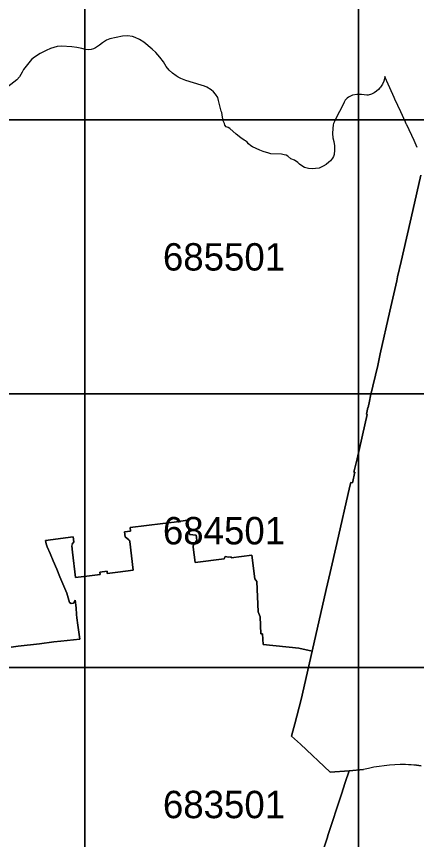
# Model space of a CAD drawing. Extents: x 25485000 to 25520000, y 6656775 to 6690000.
# Drawn here: x 25500750 to 25502211, y 6683372 to 6686378 of the extents above; entities that cross this region are included whole.
import ezdxf

# ---------------------------------------------------------------- set-up
doc = ezdxf.new("R2010")
doc.units = 0
doc.layers.add('Level 63', color=7, linetype='Continuous')

msp = doc.modelspace()

# ---------------------------------------------------------------- linework, layer by layer
at = {"layer": 'Level 63'}
for points in [[(25500000, 6686000), (25501000, 6686000), (25501000, 6687000), (25500000, 6687000)], [(25501000, 6686000), (25502000, 6686000), (25502000, 6687000), (25501000, 6687000)], [(25502000, 6686000), (25503000, 6686000), (25503000, 6687000), (25502000, 6687000)], [(25500000, 6685000), (25501000, 6685000), (25501000, 6686000), (25500000, 6686000)], [(25501000, 6685000), (25502000, 6685000), (25502000, 6686000), (25501000, 6686000)], [(25502000, 6685000), (25503000, 6685000), (25503000, 6686000), (25502000, 6686000)], [(25500000, 6684000), (25501000, 6684000), (25501000, 6685000), (25500000, 6685000)], [(25501000, 6684000), (25502000, 6684000), (25502000, 6685000), (25501000, 6685000)], [(25502000, 6684000), (25503000, 6684000), (25503000, 6685000), (25502000, 6685000)], [(25500000, 6683000), (25501000, 6683000), (25501000, 6684000), (25500000, 6684000)], [(25501000, 6683000), (25502000, 6683000), (25502000, 6684000), (25501000, 6684000)], [(25502000, 6683000), (25503000, 6683000), (25503000, 6684000), (25502000, 6684000)]]:
    msp.add_lwpolyline(points, close=True, dxfattribs=at)
for points in [[(25502214, 6685899.6), (25502202.2, 6685925), (25502175.7, 6685982.4), (25502175.2, 6685983.4), (25502173.8, 6685986.3), (25502171.5, 6685991.4), (25502153.7, 6686030.1), (25502132.6, 6686076.5), (25502130.1, 6686082), (25502102.9, 6686142), (25502102, 6686143.9), (25502095.5, 6686158.3), (25502094, 6686149.6), (25502091.6, 6686141.6), (25502086.9, 6686130.7), (25502079.6, 6686119.4), (25502077.2, 6686116.8), (25502072.5, 6686111.6), (25502065.4, 6686105.2), (25502056.8, 6686099.3), (25502046.4, 6686093.9), (25502034.6, 6686090.8), (25502029.8, 6686090.2), (25502010.1, 6686093), (25502002, 6686093.1), (25501993.7, 6686092.7), (25501977, 6686090), (25501972.2, 6686088.4), (25501963.1, 6686083.8), (25501957.6, 6686079.6), (25501950.5, 6686072.2), (25501946.6, 6686065.3), (25501942.3, 6686054.5), (25501930.4, 6686030.7), (25501922, 6686014.9), (25501911.6, 6685994.6), (25501908.7, 6685987.5), (25501907.3, 6685982.4), (25501905.3, 6685968.9), (25501904.7, 6685951), (25501906, 6685935.1), (25501909.1, 6685920.8), (25501911.6, 6685905.4), (25501912.1, 6685889.5), (25501910.5, 6685873.9), (25501908, 6685867), (25501904.4, 6685860.4), (25501897.2, 6685851.2), (25501891.3, 6685845.6), (25501881.1, 6685837.6), (25501870.6, 6685830.7), (25501856.2, 6685824.4), (25501842.7, 6685822.3), (25501832.4, 6685821.8), (25501816.6, 6685822.4), (25501802.2, 6685826.5), (25501795.6, 6685830.1), (25501783.6, 6685838.8), (25501778, 6685844.4), (25501765.7, 6685853.6), (25501752.1, 6685858.3), (25501741.6, 6685867.5), (25501735, 6685870.8), (25501727.8, 6685873.1), (25501718.1, 6685874.7), (25501679.7, 6685876.8), (25501672.3, 6685878.6), (25501650.8, 6685884.7), (25501638.8, 6685889.4), (25501612.5, 6685901.9), (25501606.1, 6685906), (25501597.9, 6685912.7), (25501592.8, 6685918.6), (25501586.9, 6685923.2), (25501581.5, 6685925.8), (25501569.8, 6685935), (25501552.1, 6685948.6), (25501529.6, 6685968.6), (25501523.3, 6685972.7), (25501515.8, 6685974.7), (25501511.5, 6685980.9), (25501509.5, 6685986.7), (25501505.4, 6685997.3), (25501503.9, 6686002.7), (25501501.3, 6686018.7), (25501499.8, 6686027.3), (25501498.2, 6686032.6), (25501491.4, 6686056.7), (25501488.6, 6686070.7), (25501485.6, 6686081.4), (25501477.6, 6686093.9), (25501470.2, 6686102.5), (25501461.3, 6686109.7), (25501446, 6686119.2), (25501436.9, 6686123.2), (25501425.4, 6686127), (25501368.6, 6686144.4), (25501350.5, 6686151.5), (25501340.4, 6686156.6), (25501333.3, 6686161.1), (25501319.8, 6686171), (25501308.3, 6686181.6), (25501297.6, 6686194.7), (25501287.3, 6686212), (25501274.1, 6686229.4), (25501259, 6686246.6), (25501246.1, 6686258.9), (25501215.3, 6686283.8), (25501199.6, 6686294.1), (25501184.2, 6686301.2), (25501174, 6686304.2), (25501156.3, 6686307.3), (25501138.1, 6686306.4), (25501091.1, 6686296), (25501079.3, 6686291.1), (25501064.2, 6686281.8), (25501053.5, 6686273.5), (25501039.2, 6686263.2), (25501031.5, 6686259.6), (25501023.1, 6686257.1), (25501014.5, 6686256.5), (25501002.1, 6686257.7), (25500989.6, 6686261.1), (25500970.4, 6686264.7), (25500952.4, 6686267.3), (25500914.7, 6686269.8), (25500899.1, 6686268.4), (25500874.5, 6686260.7), (25500858.9, 6686254), (25500836.4, 6686242.2), (25500815.8, 6686229.8), (25500805.3, 6686220.9), (25500776.4, 6686184.3), (25500770.6, 6686175), (25500760.9, 6686157.8), (25500752.1, 6686146.3), (25500692.4, 6686100.4)], [(25500952, 6684444.6), (25500955, 6684421.2), (25500966.4, 6684329), (25501016.4, 6684335.5), (25501056.1, 6684340.5), (25501055.2, 6684348.4), (25501081.1, 6684351.7), (25501082, 6684343.8), (25501120, 6684348.7), (25501176.6, 6684356.1), (25501164.3, 6684460.4), (25501164.3, 6684460.7), (25501164.3, 6684460.9), (25501164.2, 6684461.2), (25501164.2, 6684461.4), (25501164.1, 6684461.6), (25501164, 6684461.9), (25501164, 6684462.1), (25501163.9, 6684462.4), (25501163.8, 6684462.6), (25501163.7, 6684462.8), (25501163.6, 6684463.1), (25501163.4, 6684463.3), (25501163.3, 6684463.5), (25501163.2, 6684463.7), (25501163.1, 6684463.9), (25501162.9, 6684464.1), (25501162.8, 6684464.4), (25501162.6, 6684464.5), (25501162.4, 6684464.7), (25501162.3, 6684464.9), (25501162.1, 6684465.1), (25501161.9, 6684465.3), (25501161.7, 6684465.5), (25501161.5, 6684465.6), (25501161.3, 6684465.8), (25501161.1, 6684465.9), (25501160.9, 6684466.1), (25501160.7, 6684466.2), (25501147.3, 6684477.7), (25501145.2, 6684496.1), (25501167.1, 6684498.6), (25501165.6, 6684511.5), (25501225.1, 6684518.9), (25501284.3, 6684526.2), (25501326, 6684531.4), (25501375.5, 6684537.9), (25501382.2, 6684485.5), (25501406.2, 6684483.6), (25501408.7, 6684464.8), (25501398.7, 6684450.9), (25501398.6, 6684450.7), (25501398.4, 6684450.4), (25501398.2, 6684450.1), (25501398, 6684449.8), (25501397.8, 6684449.5), (25501397.7, 6684449.2), (25501397.5, 6684448.9), (25501397.3, 6684448.5), (25501397.2, 6684448.2), (25501397.1, 6684447.9), (25501396.9, 6684447.6), (25501396.8, 6684447.2), (25501396.7, 6684446.9), (25501396.5, 6684446.5), (25501396.4, 6684446.2), (25501396.3, 6684445.9), (25501396.2, 6684445.5), (25501396.2, 6684445.2), (25501396.1, 6684444.8), (25501396, 6684444.5), (25501396, 6684444.1), (25501395.9, 6684443.8), (25501395.9, 6684443.4), (25501395.8, 6684443.1), (25501395.8, 6684442.7), (25501395.8, 6684442.3), (25501395.8, 6684442), (25501395.8, 6684441.6), (25501395.8, 6684441.3), (25501395.8, 6684440.9), (25501395.8, 6684440.6), (25501395.8, 6684440.2), (25501395.8, 6684439.8), (25501395.9, 6684439.5), (25501403.2, 6684383.9), (25501508.7, 6684397.3), (25501511.9, 6684405.2), (25501524.2, 6684403.3), (25501534.1, 6684404.5), (25501534.6, 6684400.6), (25501610.2, 6684410.1), (25501620.5, 6684323.6), (25501627.9, 6684314.5), (25501632.7, 6684203.5), (25501639.9, 6684184.8), (25501642.2, 6684123.9), (25501649.1, 6684123.2), (25501650.9, 6684084.1), (25501781.5, 6684071.2), (25501830.2, 6684060), (25501881.8, 6684285.2), (25501895.9, 6684346.9), (25501920.3, 6684453.2), (25501968.3, 6684662.6), (25501971.3, 6684676), (25501977.2, 6684674.6), (25501985.9, 6684713.2), (25501983, 6684713.8), (25501994, 6684762.1), (25502031, 6684924.9), (25502028.3, 6684925.6), (25502033.9, 6684949.8), (25502034.2, 6684949.6), (25502039.1, 6684972.5), (25502043.8, 6684992.7), (25502069.5, 6685103.7), (25502077.9, 6685139.8), (25502078.2, 6685145.8), (25502114, 6685301.6), (25502128.3, 6685364.9), (25502139.2, 6685412.8), (25502142.3, 6685426.8), (25502155.1, 6685482.6), (25502197.7, 6685669.2), (25502227.1, 6685798.4)], [(25502227.1, 6685798.4), (25502197.7, 6685669.2), (25502155.1, 6685482.6), (25502142.3, 6685426.8), (25502139.2, 6685412.8), (25502128.3, 6685364.9), (25502114, 6685301.6), (25502078.2, 6685145.8), (25502077.9, 6685139.8), (25502069.5, 6685103.7), (25502043.8, 6684992.7), (25502039.1, 6684972.5), (25502034.2, 6684949.6), (25502033.9, 6684949.8), (25502028.3, 6684925.6), (25502031, 6684924.9), (25501994, 6684762.1), (25501983, 6684713.8), (25501985.9, 6684713.2), (25501977.2, 6684674.6), (25501971.3, 6684676), (25501968.3, 6684662.6), (25501920.3, 6684453.2), (25501895.9, 6684346.9), (25501881.8, 6684285.2), (25501830.2, 6684060), (25501789.6, 6683883), (25501767.2, 6683795), (25501760.2, 6683767.7), (25501755.2, 6683749.4)], [(25501847.4, 6683262.5), (25501885.7, 6683380.5), (25501887.7, 6683386.7), (25501936.8, 6683537.9), (25501950.7, 6683580.2), (25501964.8, 6683622.8), (25501896.1, 6683618.6), (25501787.7, 6683720.7), (25501755.2, 6683749.4), (25501760.2, 6683767.7), (25501767.2, 6683795), (25501789.6, 6683883), (25501830.2, 6684060), (25501781.5, 6684071.2), (25501650.9, 6684084.1), (25501649.1, 6684123.2), (25501642.2, 6684123.9), (25501639.9, 6684184.8), (25501632.7, 6684203.5), (25501627.9, 6684314.5), (25501620.5, 6684323.6), (25501610.2, 6684410.1), (25501534.6, 6684400.6), (25501534.1, 6684404.5), (25501524.2, 6684403.3), (25501511.9, 6684405.2), (25501508.7, 6684397.3), (25501403.2, 6684383.9), (25501395.9, 6684439.5), (25501395.8, 6684439.8), (25501395.8, 6684440.2), (25501395.8, 6684440.6), (25501395.8, 6684440.9), (25501395.8, 6684441.3), (25501395.8, 6684441.6), (25501395.8, 6684442), (25501395.8, 6684442.3), (25501395.8, 6684442.7), (25501395.8, 6684443.1), (25501395.9, 6684443.4), (25501395.9, 6684443.8), (25501396, 6684444.1), (25501396, 6684444.5), (25501396.1, 6684444.8), (25501396.2, 6684445.2), (25501396.2, 6684445.5), (25501396.3, 6684445.9), (25501396.4, 6684446.2), (25501396.5, 6684446.5), (25501396.7, 6684446.9), (25501396.8, 6684447.2), (25501396.9, 6684447.6), (25501397.1, 6684447.9), (25501397.2, 6684448.2), (25501397.3, 6684448.5), (25501397.5, 6684448.9), (25501397.7, 6684449.2), (25501397.8, 6684449.5), (25501398, 6684449.8), (25501398.2, 6684450.1), (25501398.4, 6684450.4), (25501398.6, 6684450.7), (25501398.7, 6684450.9), (25501408.7, 6684464.8), (25501406.2, 6684483.6), (25501382.2, 6684485.5), (25501375.5, 6684537.9), (25501326, 6684531.4), (25501284.3, 6684526.2), (25501225.1, 6684518.9), (25501165.6, 6684511.5), (25501167.1, 6684498.6), (25501145.2, 6684496.1), (25501147.3, 6684477.7), (25501160.7, 6684466.2), (25501160.9, 6684466.1), (25501161.1, 6684465.9), (25501161.3, 6684465.8), (25501161.5, 6684465.6), (25501161.7, 6684465.5), (25501161.9, 6684465.3), (25501162.1, 6684465.1), (25501162.3, 6684464.9), (25501162.4, 6684464.7), (25501162.6, 6684464.5), (25501162.8, 6684464.4), (25501162.9, 6684464.1), (25501163.1, 6684463.9), (25501163.2, 6684463.7), (25501163.3, 6684463.5), (25501163.4, 6684463.3), (25501163.6, 6684463.1), (25501163.7, 6684462.8), (25501163.8, 6684462.6), (25501163.9, 6684462.4), (25501164, 6684462.1), (25501164, 6684461.9), (25501164.1, 6684461.6), (25501164.2, 6684461.4), (25501164.2, 6684461.2), (25501164.3, 6684460.9), (25501164.3, 6684460.7), (25501164.3, 6684460.4), (25501176.6, 6684356.1), (25501120, 6684348.7), (25501082, 6684343.8), (25501081.1, 6684351.7), (25501055.2, 6684348.4), (25501056.1, 6684340.5), (25501016.4, 6684335.5), (25500966.4, 6684329), (25500955, 6684421.2), (25500952, 6684444.6)], [(25500953.4, 6684450.2), (25500960.3, 6684459.8), (25500957.8, 6684477.7), (25500856.8, 6684463.6), (25500858.6, 6684451.7), (25500862.7, 6684441.5), (25500873, 6684417.2), (25500884.2, 6684390.1), (25500897.2, 6684359.1), (25500909, 6684331.6), (25500923.1, 6684297.2), (25500933.9, 6684272.1), (25500934.3, 6684271.3), (25500944.4, 6684237.4), (25500950.3, 6684234.1), (25500958.2, 6684235.1), (25500965.2, 6684246.5), (25500968.8, 6684218.3), (25500969, 6684193.3), (25500971.2, 6684181.8), (25500974.6, 6684155.5), (25500981.3, 6684103.9), (25500911.8, 6684096.3), (25500886.4, 6684093.5), (25500834.2, 6684087.3), (25500756.5, 6684078.4), (25500730.4, 6684074.3)], [(25500730.4, 6684074.3), (25500756.5, 6684078.4), (25500834.2, 6684087.3), (25500886.4, 6684093.5), (25500911.8, 6684096.3), (25500981.3, 6684103.9), (25500974.6, 6684155.5), (25500971.2, 6684181.8), (25500969, 6684193.3), (25500968.8, 6684218.3), (25500965.2, 6684246.5), (25500958.2, 6684235.1), (25500950.3, 6684234.1), (25500944.4, 6684237.4), (25500934.3, 6684271.3), (25500933.9, 6684272.1), (25500923.1, 6684297.2), (25500909, 6684331.6), (25500897.2, 6684359.1), (25500884.2, 6684390.1), (25500873, 6684417.2), (25500862.7, 6684441.5), (25500858.6, 6684451.7), (25500856.8, 6684463.6), (25500957.8, 6684477.7), (25500960.3, 6684459.8), (25500953.4, 6684450.2)], [(25501755.2, 6683749.4), (25501787.7, 6683720.7), (25501896.1, 6683618.6), (25501964.8, 6683622.8), (25502017.1, 6683627.3)], [(25502017.1, 6683627.3), (25501964.8, 6683622.8), (25501950.7, 6683580.2), (25501936.8, 6683537.9), (25501887.7, 6683386.7), (25501885.7, 6683380.5), (25501847.4, 6683262.5)], [(25502228.6, 6683641.7), (25502211.4, 6683643.4)], [(25502211.4, 6683643.4), (25502228.6, 6683641.7)]]:
    msp.add_lwpolyline(points, dxfattribs=at)
for centre, radius, start, end in [((25500959.9, 6684445.6), 8, 144.4853, 187.1085), ((25500959.9, 6684445.6), 8, 144.4853, 187.1085), ((25502161.5, 6683065.6), 580, 89.0119, 104.413), ((25502161.5, 6683065.6), 580, 89.0119, 104.413), ((25502161.5, 6683065.6), 580, 85.0647, 89.0117), ((25502161.5, 6683065.6), 580, 85.0647, 89.0117)]:
    msp.add_arc(centre, radius, start, end, dxfattribs=at)

# ---------------------------------------------------------------- texts
for s, p in [('685501', (25501285.1, 6685450)), ('684501', (25501285.1, 6684450)), ('683501', (25501285.1, 6683450))]:
    msp.add_text(s, height=100, dxfattribs=at).set_placement(p)

doc.saveas('drawing.dxf')
